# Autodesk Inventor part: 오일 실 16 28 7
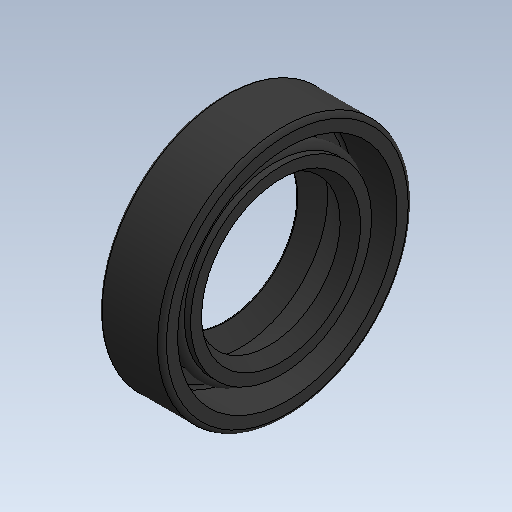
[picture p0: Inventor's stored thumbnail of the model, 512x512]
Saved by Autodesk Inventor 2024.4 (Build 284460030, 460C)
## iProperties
Created: 2026-09
Part Number: 오일 실 16 28 7
Material: 고무
Description: 오일-실
Document SubType Name: Modeling
Designer: user
Density: 0.93 g/cm^3
Appearance: 기본값
Sending System: Autodesk Inventor 2027
Preprocessor: ST-DEVELOPER v20.1
Author: jhkim
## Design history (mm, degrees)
feature "Solid1"
node "솔리드1"
